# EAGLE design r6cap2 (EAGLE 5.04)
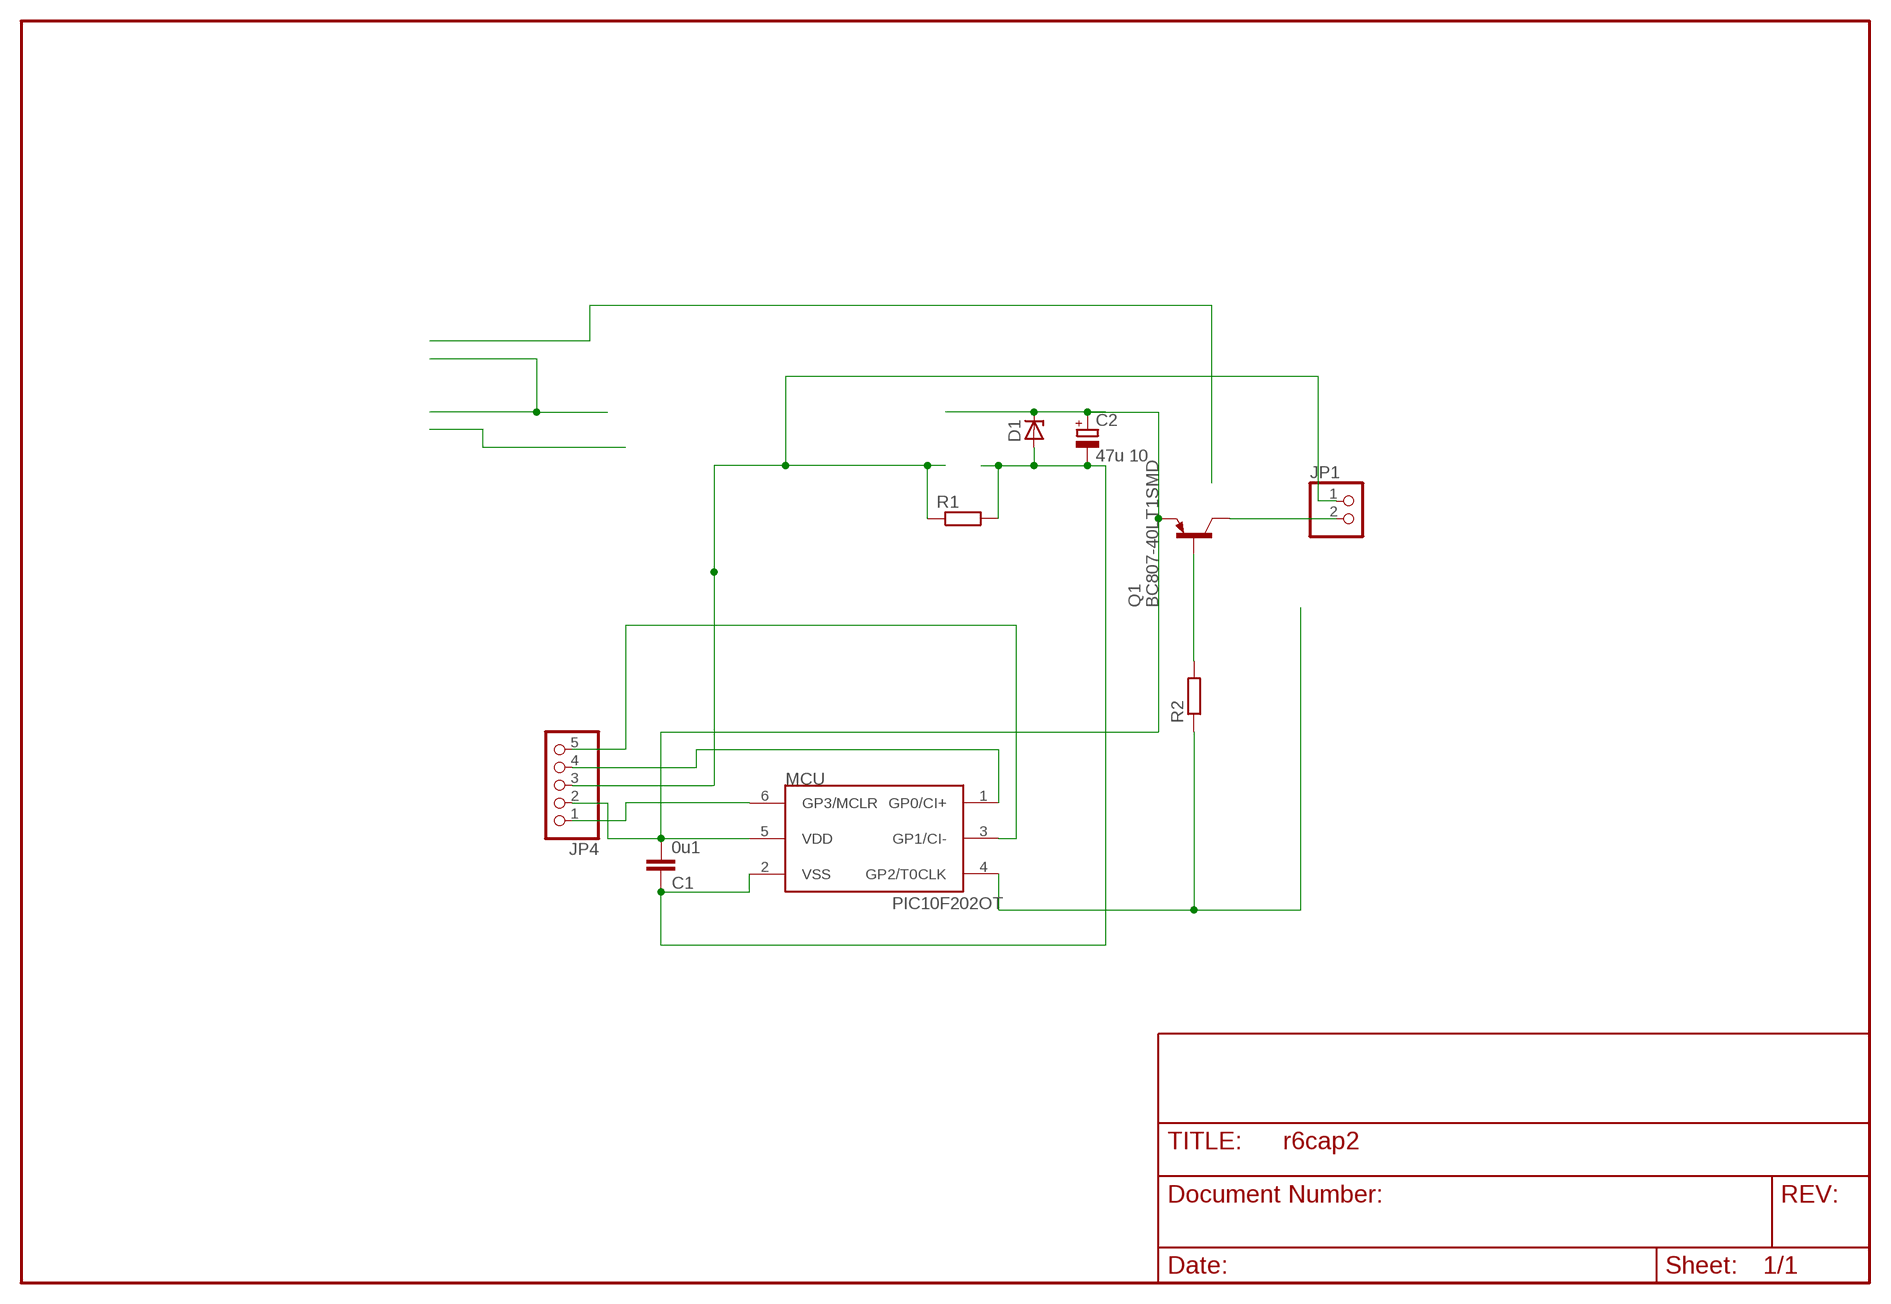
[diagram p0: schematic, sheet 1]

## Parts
C1  0u1  C-EUC0805  [C0805]
C2  47u 10  CPOL-EUE2-5  [E2-5]
D1  ZENER-DIODESOT23  [SOT23]
JP1  PINHD-1X2  [1X02]
JP4  PINHD-1X5  [1X05]
MCU  PIC10F202OT  [SOT23-6]
Q1  BC807-40LT1SMD  [SOT23-BEC]
R1  R-EU_R0805  [R0805]
R2  R-EU_R0805  [R0805]

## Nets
GATE: MCU.4(GP2/T0CLK) R2.1
GP0: JP4.4 MCU.1(GP0/CI+)
GP1: JP4.5 MCU.3(GP1/CI-)
GP3: JP4.1 MCU.6(GP3/MCLR)
N$2: C1.1 C2.- D1.1(A) MCU.2(VSS) R1.2
N$3: Q1.B R2.2
N$4: JP1.2 Q1.C
VDD: C1.2 C2.+ D1.3(C) JP4.2 MCU.5(VDD) Q1.E
VSS: JP1.1 JP4.3 R1.1

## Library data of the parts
C1 = rcl:C-EU: CAPACITOR, European symbol
C2 = rcl:CPOL-EU: POLARIZED CAPACITOR, European symbol
D1 = diode-1:ZENER-DIODE: Z-Diode
JP1 = pinhead:PINHD-1X2: PIN HEADER
JP4 = pinhead(2):PINHD-1X5: PIN HEADER
MCU = microchip-3:PIC10F2*: uPC nW 0,25/0,5k Program Flash memory Comparator
Q1 = transistor-pnp:BC807*: PNP Transistror
R1 R2 = rcl-2:R-EU_: RESISTOR, European symbol

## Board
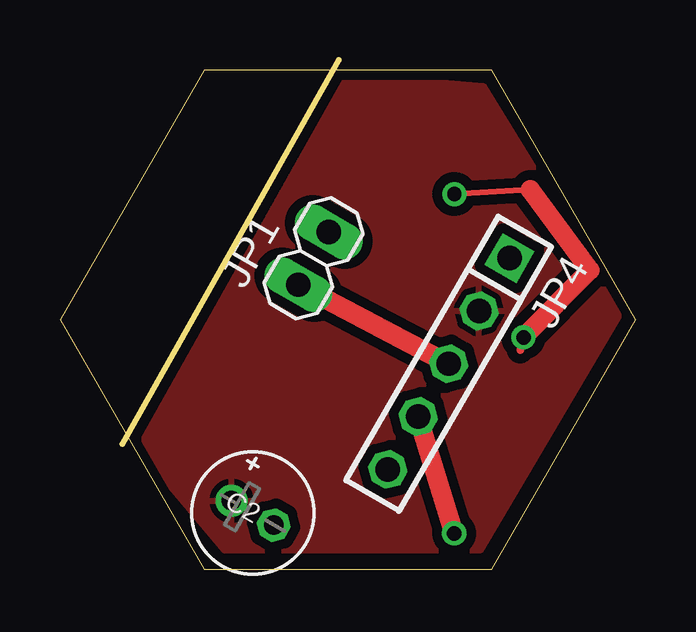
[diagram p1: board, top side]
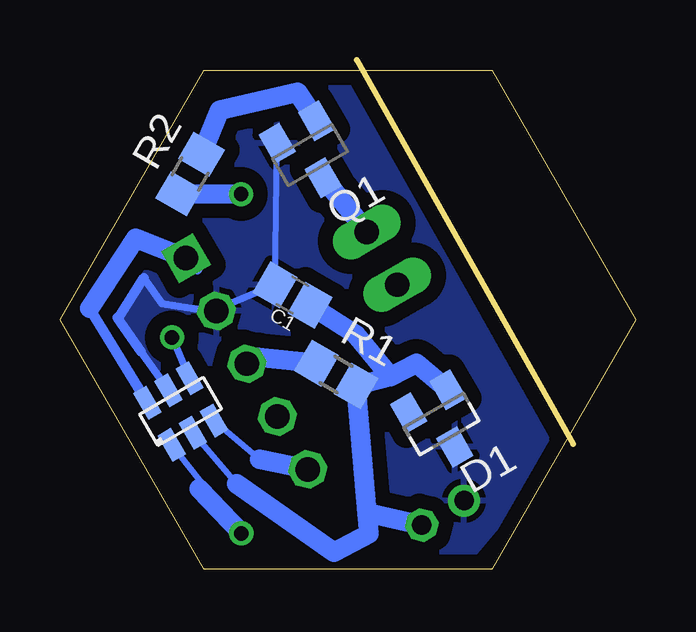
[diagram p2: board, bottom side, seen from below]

Size 24 x 21.21 mm. Coordinates in mm from the lower left corner, seen from the top.
Outline: 11.62,21.21 2.6,5.21
Outline: 6,0 18,0 24,10.39 18,20.78 6,20.78 0,10.39 6,0
Copper layers (1*16): Top 0.035mm / dielectric 1.5mm / Bottom 0.035mm
Design rules "default": minimum track width 10mil, minimum drill 24mil, track to track 8mil, track to pad 8mil, pad to pad 8mil, via to via 8mil, smd to smd 8mil, copper to edge 8mil, drill to drill 8mil, minimum pad ring 10mil, minimum via ring 8mil, stop-mask expansion 4mil, vias tented up to drill 0mil, thermal gap 10mil

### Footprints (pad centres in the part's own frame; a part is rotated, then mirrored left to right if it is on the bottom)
C0805 = smd 1.3 x 1.5: 1 -0.85,0; 2 0.85,0
E2-5 = drill 0.813 pad 1.27 round: + -1.016,0 | drill 0.813 pad 1.27 octagon: - 1.016,0
SOT23 = smd 1 x 1.4: 1 -0.95,-1.1; 2 0.95,-1.1; 3 0,1.1
1X02 = drill 1.016 long: 1 -1.27,0; 2 1.27,0
1X05 = drill 1.016 square: 1 -5.08,0 | drill 1.016 octagon: 2 -2.54,0; 3 0,0; 4 2.54,0; 5 5.08,0
SOT23-6 = smd 0.635 x 1.27: 1 -1.016,-1.016; 2 0,-1.016; 3 1.016,-1.016; 4 1.016,1.016; 5 0,1.016; 6 -1.016,1.016
SOT23-BEC = smd 1 x 1.4: B -0.95,-1.1; C 0,1.1; E 0.95,-1.1
R0805 = smd 1.3 x 1.5: 1 -0.95,0; 2 0.95,0

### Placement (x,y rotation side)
C1  14.3,11.42 150 bottom
C2  8.04,2.34 330 top
D1  8.09,6.04 210 bottom
JP1  10.57,12.95 60 top
JP4  16.21,8.55 240 top
MCU  18.97,6.56 30 bottom
Q1  13.57,17.25 210 bottom
R1  12.49,8.1 330 bottom
R2  18.57,16.45 60 bottom

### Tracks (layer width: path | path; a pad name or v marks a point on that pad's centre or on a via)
GATE  (via drill 0.6)
  Top 0.254: 19.62,15.81 v16.45,15.62
  Top 0.305: v19.33,9.65 19.19,9.12
  Top 0.813: v19.33,9.65 22.1,12.45 19.62,15.81
  Bottom 0.305: MCU.4 v19.33,9.65
  Bottom 0.813: v16.45,15.62 R2.1
GP0  (via drill 0.6)
  Top 0.813: v16.44,1.49 JP4.4
  Bottom 0.254: v16.44,1.49 MCU.1
  Bottom 0.406: MCU.1 19.34,4.93
  Bottom 0.813: v16.44,1.49 18.2,3.35
GP1
  Bottom 0.254: 15.68,4.57 MCU.3
  Bottom 0.813: JP4.5 15.68,4.57
GP3
  Bottom 0.406: MCU.6 21.81,9.3 22.76,10.86 | JP4.1 18.73,12.89 18.28,12.49
  Bottom 0.813: JP4.1 20.84,13.78 22.76,10.86
N$2
  Bottom 0.254: 16.64,3.56 MCU.2
  Bottom 0.813: 16.64,3.56 12.57,0.7 11.11,1.46 11.19,2.34 | D1.1 9.14,8.57 10.22,8.02 | 10.22,8.02 R1.2 11.19,2.34 | C1.1 11.68,9.78 10.22,8.02 | C2.- 11.19,2.34
N$3
  Bottom 0.813: R2.2 17.34,19.11 14.1,19.88 Q1.B
N$4
  Bottom 0.813: JP1.2 Q1.C
VDD
  Bottom 0.254: C1.2 Q1.E
  Bottom 0.305: C1.2 17.44,10.84 JP4.2 18.13,10.81 19.74,11.05 20.5,12.13 | 20.63,9.06 MCU.5
  Bottom 0.406: 20.63,9.06 21.61,10.48 21.57,10.45 20.5,12.13
  pour Top (isolate 0.406): 11.75,20.64 17.65,20.13 23.43,10.73 17.53,0.76 6.86,0.76 3.17,5.14 7.11,12.38
  pour Bottom (isolate 0.61): 11.68,20.45 17.59,19.94 23.37,10.54 17.46,0.57 6.79,0.57 3.11,4.95 7.05,12.19
VSS
  Top 0.813: JP1.1 JP4.3
  Bottom 0.254: JP4.3 15.75,8.83
  Bottom 0.813: 15.75,8.83 R1.1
